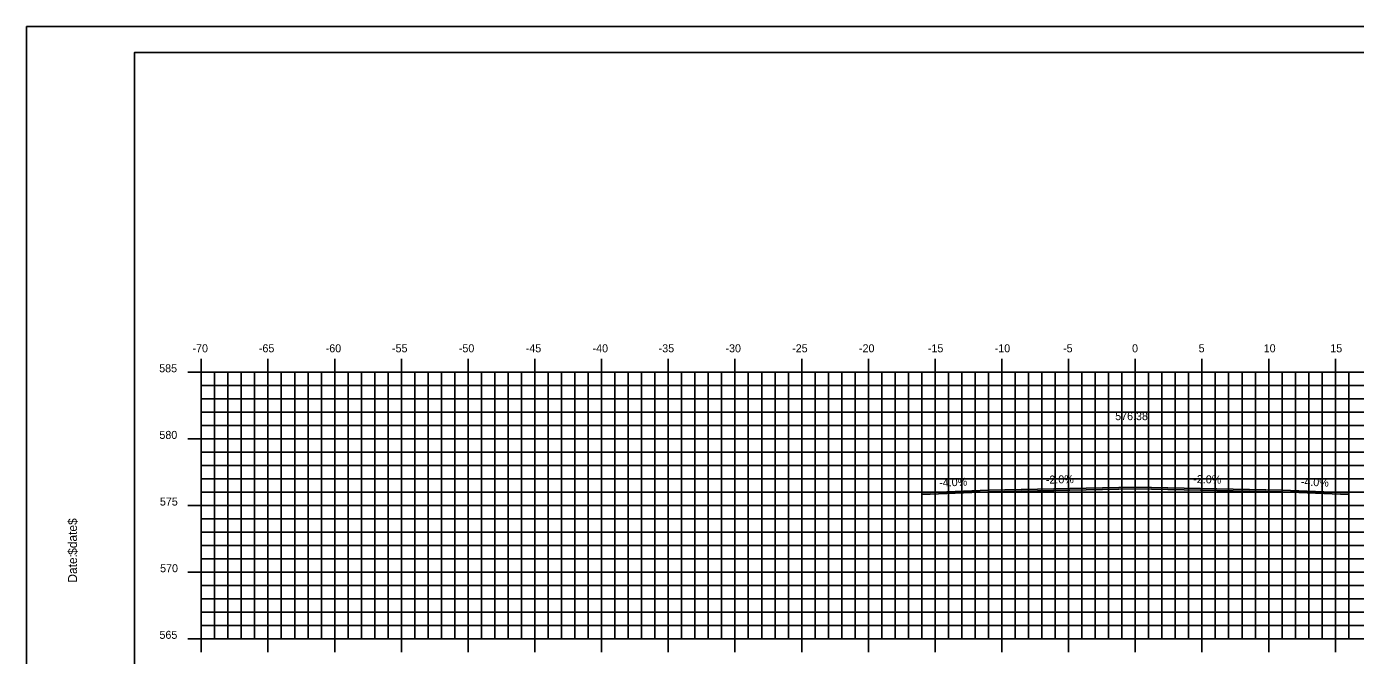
# Model space of a CAD drawing. Extents: x 1060781 to 1060951, y 779716 to 779826.
# Drawn here: x 1060780.7 to 1060880.3, y 779778.5 to 779825.6 of the extents above; entities that cross this region are included whole.
import ezdxf

# ---------------------------------------------------------------- set-up
doc = ezdxf.new("R2010")
doc.units = 0
for name, color, linetype in [('ANNOTATION', 7, 'Continuous'), ('BORDER', 7, 'Continuous'), ('D_Roadway_Centerline', 7, 'Continuous'), ('D_Roadway_Centerline_Text', 7, 'Continuous'), ('D_Roadway_Edge_TW_Mill_Overlay', 7, 'Continuous'), ('H_V ANNOTATION', 7, 'Continuous'), ('MAJOR', 7, 'Continuous'), ('MINOR', 7, 'Continuous'), ('PLOT BOUNDARY', 7, 'Continuous')]:
    doc.layers.add(name, color=color, linetype=linetype)

msp = doc.modelspace()

# ---------------------------------------------------------------- linework, layer by layer
at = {"layer": 'BORDER'}
msp.add_lwpolyline([(1060788.836, 779718.706), (1060948.836, 779718.706), (1060948.836, 779823.706), (1060788.836, 779823.706)], close=True, dxfattribs=at)
at = {"layer": 'D_Roadway_Centerline'}
msp.add_lwpolyline([(1060847.836, 779790.663), (1060852.836, 779790.863), (1060863.836, 779791.083), (1060874.836, 779790.863), (1060879.836, 779790.663)], dxfattribs=at)
at = {"layer": 'D_Roadway_Edge_TW_Mill_Overlay'}
msp.add_lwpolyline([(1060863.836, 779791.083), (1060874.836, 779790.863), (1060879.836, 779790.663), (1060879.836, 779790.538), (1060874.836, 779790.738), (1060863.836, 779790.958), (1060852.836, 779790.738), (1060847.836, 779790.538), (1060847.836, 779790.663), (1060852.836, 779790.863)], close=True, dxfattribs=at)
at = {"layer": 'MAJOR'}
for p, q in [((1060793.836, 779800.708), (1060793.836, 779799.706)), ((1060798.836, 779800.708), (1060798.836, 779799.706)), ((1060803.836, 779800.708), (1060803.836, 779799.706)), ((1060808.836, 779800.708), (1060808.836, 779799.706)), ((1060813.836, 779800.708), (1060813.836, 779799.706)), ((1060818.836, 779800.708), (1060818.836, 779799.706)), ((1060823.836, 779800.708), (1060823.836, 779799.706)), ((1060828.836, 779800.708), (1060828.836, 779799.706)), ((1060833.836, 779800.708), (1060833.836, 779799.706)), ((1060838.836, 779800.708), (1060838.836, 779799.706)), ((1060843.836, 779800.708), (1060843.836, 779799.706)), ((1060848.836, 779800.708), (1060848.836, 779799.706)), ((1060853.836, 779800.708), (1060853.836, 779799.706)), ((1060858.836, 779800.708), (1060858.836, 779799.706)), ((1060863.836, 779800.708), (1060863.836, 779799.706)), ((1060868.836, 779800.708), (1060868.836, 779799.706)), ((1060873.836, 779800.708), (1060873.836, 779799.706)), ((1060878.836, 779800.708), (1060878.836, 779799.706)), ((1060792.834, 779799.706), (1060793.836, 779799.706)), ((1060793.836, 779799.706), (1060933.836, 779799.706)), ((1060793.836, 779779.706), (1060793.836, 779799.706)), ((1060793.836, 779779.706), (1060793.836, 779799.706)), ((1060793.836, 779799.706), (1060933.836, 779799.706)), ((1060798.836, 779779.706), (1060798.836, 779799.706)), ((1060803.836, 779779.706), (1060803.836, 779799.706)), ((1060808.836, 779779.706), (1060808.836, 779799.706)), ((1060813.836, 779779.706), (1060813.836, 779799.706)), ((1060818.836, 779779.706), (1060818.836, 779799.706)), ((1060823.836, 779779.706), (1060823.836, 779799.706)), ((1060828.836, 779779.706), (1060828.836, 779799.706)), ((1060833.836, 779779.706), (1060833.836, 779799.706)), ((1060838.836, 779779.706), (1060838.836, 779799.706)), ((1060843.836, 779779.706), (1060843.836, 779799.706)), ((1060848.836, 779779.706), (1060848.836, 779799.706)), ((1060853.836, 779779.706), (1060853.836, 779799.706)), ((1060858.836, 779779.706), (1060858.836, 779799.706)), ((1060863.836, 779779.706), (1060863.836, 779799.706)), ((1060868.836, 779779.706), (1060868.836, 779799.706)), ((1060873.836, 779779.706), (1060873.836, 779799.706)), ((1060878.836, 779779.706), (1060878.836, 779799.706)), ((1060792.834, 779794.706), (1060793.836, 779794.706)), ((1060793.836, 779794.706), (1060933.836, 779794.706)), ((1060792.834, 779789.706), (1060793.836, 779789.706)), ((1060793.836, 779789.706), (1060933.836, 779789.706)), ((1060792.834, 779784.706), (1060793.836, 779784.706)), ((1060793.836, 779784.706), (1060933.836, 779784.706)), ((1060792.834, 779779.706), (1060793.836, 779779.706)), ((1060793.836, 779779.706), (1060933.836, 779779.706)), ((1060793.836, 779779.706), (1060933.836, 779779.706)), ((1060793.836, 779778.704), (1060793.836, 779779.706)), ((1060798.836, 779778.704), (1060798.836, 779779.706)), ((1060803.836, 779778.704), (1060803.836, 779779.706)), ((1060808.836, 779778.704), (1060808.836, 779779.706)), ((1060813.836, 779778.704), (1060813.836, 779779.706)), ((1060818.836, 779778.704), (1060818.836, 779779.706)), ((1060823.836, 779778.704), (1060823.836, 779779.706)), ((1060828.836, 779778.704), (1060828.836, 779779.706)), ((1060833.836, 779778.704), (1060833.836, 779779.706)), ((1060838.836, 779778.704), (1060838.836, 779779.706)), ((1060843.836, 779778.704), (1060843.836, 779779.706)), ((1060848.836, 779778.704), (1060848.836, 779779.706)), ((1060853.836, 779778.704), (1060853.836, 779779.706)), ((1060858.836, 779778.704), (1060858.836, 779779.706)), ((1060863.836, 779778.704), (1060863.836, 779779.706)), ((1060868.836, 779778.704), (1060868.836, 779779.706)), ((1060873.836, 779778.704), (1060873.836, 779779.706)), ((1060878.836, 779778.704), (1060878.836, 779779.706))]:
    msp.add_line(p, q, dxfattribs=at)
at = {"layer": 'MINOR'}
for p, q in [((1060794.836, 779779.706), (1060794.836, 779799.706)), ((1060795.836, 779779.706), (1060795.836, 779799.706)), ((1060796.836, 779779.706), (1060796.836, 779799.706)), ((1060797.836, 779779.706), (1060797.836, 779799.706)), ((1060799.836, 779779.706), (1060799.836, 779799.706)), ((1060800.836, 779779.706), (1060800.836, 779799.706)), ((1060801.836, 779779.706), (1060801.836, 779799.706)), ((1060802.836, 779779.706), (1060802.836, 779799.706)), ((1060804.836, 779779.706), (1060804.836, 779799.706)), ((1060805.836, 779779.706), (1060805.836, 779799.706)), ((1060806.836, 779779.706), (1060806.836, 779799.706)), ((1060807.836, 779779.706), (1060807.836, 779799.706)), ((1060809.836, 779779.706), (1060809.836, 779799.706)), ((1060810.836, 779779.706), (1060810.836, 779799.706)), ((1060811.836, 779779.706), (1060811.836, 779799.706)), ((1060812.836, 779779.706), (1060812.836, 779799.706)), ((1060814.836, 779779.706), (1060814.836, 779799.706)), ((1060815.836, 779779.706), (1060815.836, 779799.706)), ((1060816.836, 779779.706), (1060816.836, 779799.706)), ((1060817.836, 779779.706), (1060817.836, 779799.706)), ((1060819.836, 779779.706), (1060819.836, 779799.706)), ((1060820.836, 779779.706), (1060820.836, 779799.706)), ((1060821.836, 779779.706), (1060821.836, 779799.706)), ((1060822.836, 779779.706), (1060822.836, 779799.706)), ((1060824.836, 779779.706), (1060824.836, 779799.706)), ((1060825.836, 779779.706), (1060825.836, 779799.706)), ((1060826.836, 779779.706), (1060826.836, 779799.706)), ((1060827.836, 779779.706), (1060827.836, 779799.706)), ((1060829.836, 779779.706), (1060829.836, 779799.706)), ((1060830.836, 779779.706), (1060830.836, 779799.706)), ((1060831.836, 779779.706), (1060831.836, 779799.706)), ((1060832.836, 779779.706), (1060832.836, 779799.706)), ((1060834.836, 779779.706), (1060834.836, 779799.706)), ((1060835.836, 779779.706), (1060835.836, 779799.706)), ((1060836.836, 779779.706), (1060836.836, 779799.706)), ((1060837.836, 779779.706), (1060837.836, 779799.706)), ((1060839.836, 779779.706), (1060839.836, 779799.706)), ((1060840.836, 779779.706), (1060840.836, 779799.706)), ((1060841.836, 779779.706), (1060841.836, 779799.706)), ((1060842.836, 779779.706), (1060842.836, 779799.706)), ((1060844.836, 779779.706), (1060844.836, 779799.706)), ((1060845.836, 779779.706), (1060845.836, 779799.706)), ((1060846.836, 779779.706), (1060846.836, 779799.706)), ((1060847.836, 779779.706), (1060847.836, 779799.706)), ((1060849.836, 779779.706), (1060849.836, 779799.706)), ((1060850.836, 779779.706), (1060850.836, 779799.706)), ((1060851.836, 779779.706), (1060851.836, 779799.706)), ((1060852.836, 779779.706), (1060852.836, 779799.706)), ((1060854.836, 779779.706), (1060854.836, 779799.706)), ((1060855.836, 779779.706), (1060855.836, 779799.706)), ((1060856.836, 779779.706), (1060856.836, 779799.706)), ((1060857.836, 779779.706), (1060857.836, 779799.706)), ((1060859.836, 779779.706), (1060859.836, 779799.706)), ((1060860.836, 779779.706), (1060860.836, 779799.706)), ((1060861.836, 779779.706), (1060861.836, 779799.706)), ((1060862.836, 779779.706), (1060862.836, 779799.706)), ((1060864.836, 779779.706), (1060864.836, 779799.706)), ((1060865.836, 779779.706), (1060865.836, 779799.706)), ((1060866.836, 779779.706), (1060866.836, 779799.706)), ((1060867.836, 779779.706), (1060867.836, 779799.706)), ((1060869.836, 779779.706), (1060869.836, 779799.706)), ((1060870.836, 779779.706), (1060870.836, 779799.706)), ((1060871.836, 779779.706), (1060871.836, 779799.706)), ((1060872.836, 779779.706), (1060872.836, 779799.706)), ((1060874.836, 779779.706), (1060874.836, 779799.706)), ((1060875.836, 779779.706), (1060875.836, 779799.706)), ((1060876.836, 779779.706), (1060876.836, 779799.706)), ((1060877.836, 779779.706), (1060877.836, 779799.706)), ((1060879.836, 779779.706), (1060879.836, 779799.706)), ((1060793.836, 779798.706), (1060933.836, 779798.706)), ((1060793.836, 779798.706), (1060794.838, 779798.706)), ((1060793.836, 779797.706), (1060933.836, 779797.706)), ((1060793.836, 779797.706), (1060794.838, 779797.706)), ((1060793.836, 779796.706), (1060933.836, 779796.706)), ((1060793.836, 779796.706), (1060794.838, 779796.706)), ((1060793.836, 779795.706), (1060933.836, 779795.706)), ((1060793.836, 779795.706), (1060794.838, 779795.706)), ((1060793.836, 779793.706), (1060933.836, 779793.706)), ((1060793.836, 779793.706), (1060794.838, 779793.706)), ((1060793.836, 779792.706), (1060933.836, 779792.706)), ((1060793.836, 779792.706), (1060794.838, 779792.706)), ((1060793.836, 779791.706), (1060933.836, 779791.706)), ((1060793.836, 779791.706), (1060794.838, 779791.706)), ((1060793.836, 779790.706), (1060933.836, 779790.706)), ((1060793.836, 779790.706), (1060794.838, 779790.706)), ((1060793.836, 779788.706), (1060933.836, 779788.706)), ((1060793.836, 779788.706), (1060794.838, 779788.706)), ((1060793.836, 779787.706), (1060933.836, 779787.706)), ((1060793.836, 779787.706), (1060794.838, 779787.706)), ((1060793.836, 779786.706), (1060933.836, 779786.706)), ((1060793.836, 779786.706), (1060794.838, 779786.706)), ((1060793.836, 779785.706), (1060933.836, 779785.706)), ((1060793.836, 779785.706), (1060794.838, 779785.706)), ((1060793.836, 779783.706), (1060933.836, 779783.706)), ((1060793.836, 779783.706), (1060794.838, 779783.706)), ((1060793.836, 779782.706), (1060933.836, 779782.706)), ((1060793.836, 779782.706), (1060794.838, 779782.706)), ((1060793.836, 779781.706), (1060933.836, 779781.706)), ((1060793.836, 779781.706), (1060794.838, 779781.706)), ((1060793.836, 779780.706), (1060933.836, 779780.706)), ((1060793.836, 779780.706), (1060794.838, 779780.706))]:
    msp.add_line(p, q, dxfattribs=at)
at = {"layer": 'PLOT BOUNDARY'}
msp.add_lwpolyline([(1060780.743, 779715.646), (1060950.743, 779715.646), (1060950.743, 779825.646), (1060780.743, 779825.646)], close=True, dxfattribs=at)

# ---------------------------------------------------------------- texts
at = {"layer": 'ANNOTATION'}
for s, rotation, p in [('-4.0%', 2.29061, (1060849.152, 779791.117)), ('-2.0%', 1.14576, (1060857.139, 779791.349)), ('-2.0%', 358.85424, (1060868.179, 779791.396)), ('-4.0%', 357.70939, (1060876.232, 779791.208))]:
    msp.add_text(s, height=0.6, rotation=rotation, dxfattribs=at).set_placement(p)
at = {"layer": 'BORDER'}
for s, p in [('$date$', (1060784.521, 779786.011)), ('Date:', (1060784.521, 779783.923))]:
    msp.add_text(s, height=0.6696, rotation=90, dxfattribs=at).set_placement(p)
at = {"layer": 'D_Roadway_Centerline_Text'}
msp.add_text('576.38', height=0.6, dxfattribs=at).set_placement((1060862.33, 779796.115))
at = {"layer": 'H_V ANNOTATION'}
for s, p in [('-70', (1060793.178, 779801.206)), ('-65', (1060798.154, 779801.206)), ('-60', (1060803.162, 779801.206)), ('-55', (1060808.132, 779801.206)), ('-50', (1060813.14, 779801.206)), ('-45', (1060818.154, 779801.206)), ('-40', (1060823.162, 779801.206)), ('-35', (1060828.116, 779801.206)), ('-30', (1060833.124, 779801.206)), ('-25', (1060838.122, 779801.206)), ('-20', (1060843.13, 779801.206)), ('-15', (1060848.293, 779801.206)), ('-10', (1060853.301, 779801.206)), ('-5', (1060858.427, 779801.206)), ('0', (1060863.595, 779801.206)), ('5', (1060868.587, 779801.206)), ('10', (1060873.461, 779801.206)), ('15', (1060878.453, 779801.206)), ('585', (1060790.682, 779799.706)), ('580', (1060790.698, 779794.706)), ('575', (1060790.735, 779789.706)), ('570', (1060790.751, 779784.706)), ('565', (1060790.703, 779779.706))]:
    msp.add_text(s, height=0.6, dxfattribs=at).set_placement(p)
at = {"layer": 'MAJOR'}
msp.add_text('-', height=0.006, dxfattribs=at).set_placement((1060793.832, 779779.706))

doc.saveas('drawing.dxf')
